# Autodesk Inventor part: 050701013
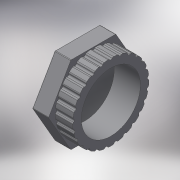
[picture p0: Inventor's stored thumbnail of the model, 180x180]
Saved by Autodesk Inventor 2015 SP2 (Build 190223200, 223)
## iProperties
Created: 2017-10
Part Number: 050701013
Material: Generic
Description: PLASSON THREADED CAP PVC 1.1/4"
Document SubType Name: Modeling
Designer: KIM
Density: 1 g/cm^3
Appearance: Default
Author: KIM
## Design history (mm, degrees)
derived "050701.ipt"
feature "Solid1::050701.ipt"
tag "TaggingFeature1"
body "Solid1"
other parameters: "d0" = 33, "d1" = 50.96, "d2" = 1, "d3" = 12, "d4" = 52, "d5" = 22, "d6" = 38.952, "d7" = 6.6, "d10" = 0, "d11" = 2.08, "d13" = 0, "d14" = 1.04, "d16" = 360 deg, "d18" = 0.52, "G_" = 38.952, "C_" = 52, "B_" = 12, "Lt_" = 22, "H_" = 33
